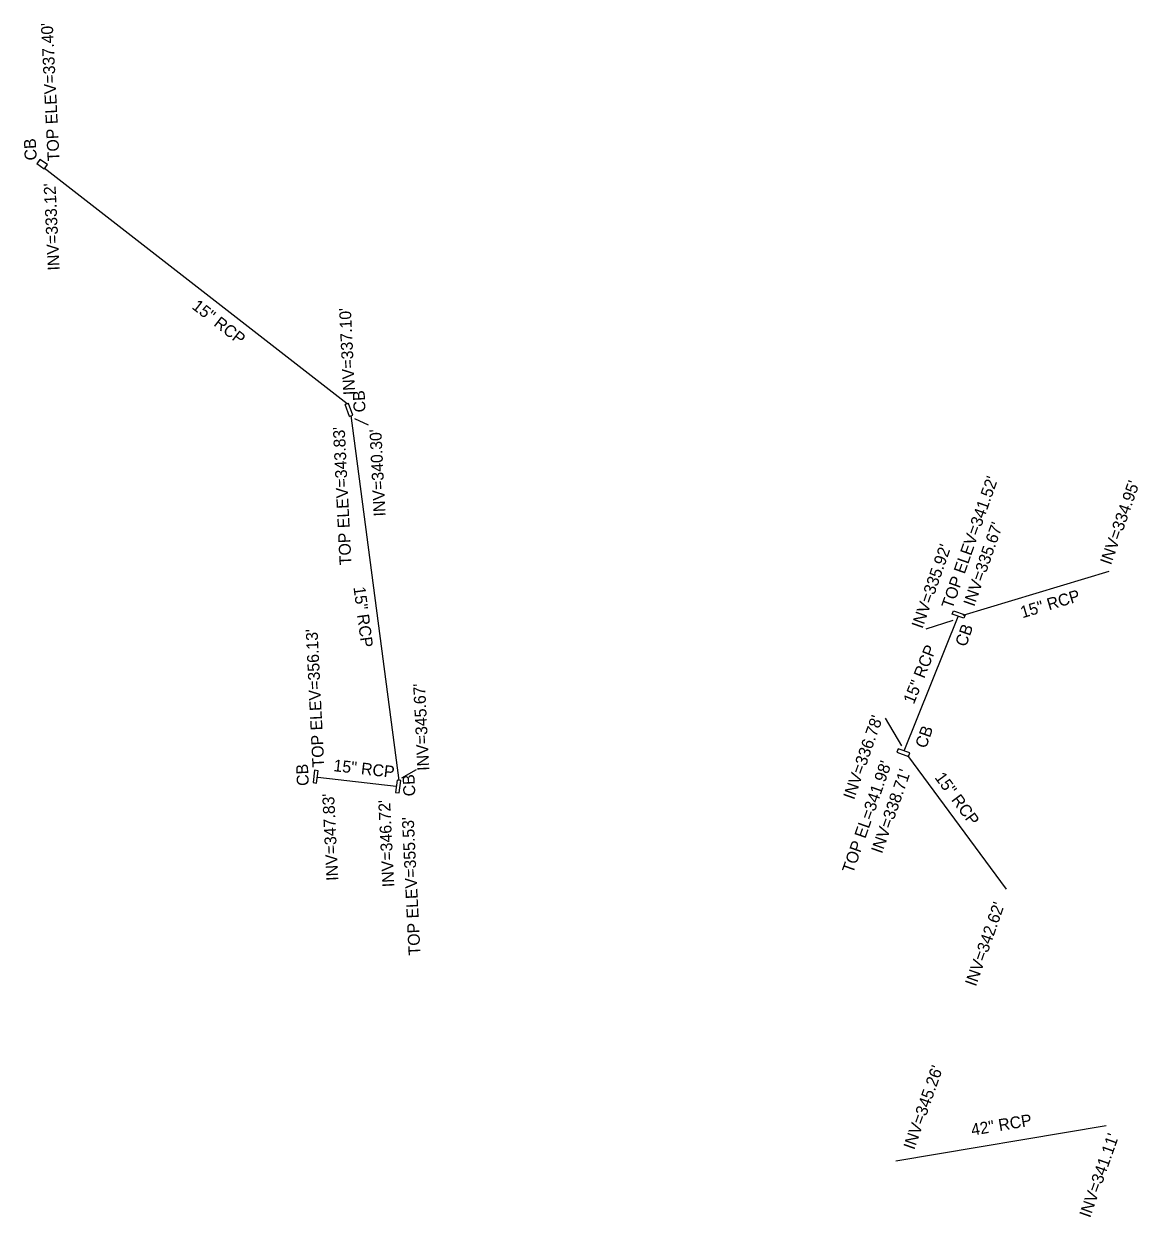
# Model space of a CAD drawing. Extents: x 1975859 to 1978323, y 778892 to 782836.
# Drawn here: x 1977337.6 to 1977712.6, y 781663.2 to 782064.9 of the extents above; entities that cross this region are included whole.
import ezdxf

# ---------------------------------------------------------------- set-up
doc = ezdxf.new("R2010")
doc.units = 0
for name, color, linetype in [('Exist Structure Minor Catch Basin', 7, 'Continuous'), ('Exist Structure Minor Catch Basin Text', 7, 'Continuous'), ('Exist Structure Minor Catch Basin Top Elevation', 7, 'Continuous'), ('Exist Structure Minor Pipes RCP 15 Inch', 7, 'Continuous'), ('Exist Structure Minor Pipes RCP 15 Inch Invert', 7, 'Continuous'), ('Exist Structure Minor Pipes RCP 15 Inch Leader', 7, 'Continuous'), ('Exist Structure Minor Pipes RCP 15 Inch Text', 7, 'Continuous'), ('Exist Structure Minor Pipes RCP 42 Inch', 7, 'Continuous'), ('Exist Structure Minor Pipes RCP 42 Inch Invert', 7, 'Continuous'), ('Exist Structure Minor Pipes RCP 42 Inch Text', 7, 'Continuous')]:
    doc.layers.add(name, color=color, linetype=linetype)

msp = doc.modelspace()

# ---------------------------------------------------------------- linework, layer by layer
at = {"layer": 'Exist Structure Minor Catch Basin'}
for p, q in [((1977344.43, 782015.95), (1977341.97, 782017.7)), ((1977447.15, 781932.75), (1977445.69, 781936.71)), ((1977650.44, 781867.32), (1977654.4, 781865.94)), ((1977631.41, 781819.67), (1977635.4, 781818.3)), ((1977436.11, 781809.29), (1977436.66, 781813.41)), ((1977463.93, 781805.98), (1977464.44, 781810.12))]:
    msp.add_line(p, q, dxfattribs=at)
for points in [[(1977344.43, 782015.95), (1977345.52, 782017.56), (1977342.95, 782019.22), (1977341.97, 782017.7)], [(1977447.15, 781932.75), (1977448.29, 781933.2), (1977446.81, 781937.1), (1977445.69, 781936.71)], [(1977654.4, 781865.94), (1977654.01, 781864.77), (1977650.02, 781866.14), (1977650.44, 781867.32)], [(1977635.4, 781818.3), (1977635.79, 781819.44), (1977631.84, 781820.82), (1977631.41, 781819.67)], [(1977436.66, 781813.41), (1977435.45, 781813.6), (1977434.93, 781809.44), (1977436.11, 781809.29)], [(1977464.44, 781810.12), (1977463.21, 781810.27), (1977462.7, 781806.12), (1977463.93, 781805.98)]]:
    msp.add_lwpolyline(points, dxfattribs=at)
at = {"layer": 'Exist Structure Minor Pipes RCP 15 Inch'}
for p, q in [((1977446.36, 781936.91), (1977344.46, 782016.26)), ((1977463.87, 781810.12), (1977447.72, 781933)), ((1977653.7, 781865.82), (1977702.94, 781880.59)), ((1977633.92, 781820.21), (1977652.04, 781865.35)), ((1977668.34, 781773.59), (1977635.08, 781818.56)), ((1977462.87, 781808.17), (1977436.48, 781811.14))]:
    msp.add_line(p, q, dxfattribs=at)
at = {"layer": 'Exist Structure Minor Pipes RCP 15 Inch Leader'}
for points in [[(1977448.83, 781931.99), (1977453.52, 781929.86)], [(1977650.22, 781864), (1977641.18, 781861.12)], [(1977633.06, 781821.82), (1977627.57, 781831.16)], [(1977464.76, 781811.07), (1977469.72, 781813.86)]]:
    msp.add_lwpolyline(points, dxfattribs=at)
at = {"layer": 'Exist Structure Minor Pipes RCP 42 Inch'}
msp.add_line((1977631.05, 781682.08), (1977701.89, 781694.05), dxfattribs=at)

# ---------------------------------------------------------------- texts
at = {"layer": 'Exist Structure Minor Catch Basin Text'}
for rotation, p in [(92.8374, (1977341.92, 782019)), (92.8374, (1977452.62, 781934.19)), (70.6265, (1977654.71, 781854.94)), (70.6265, (1977641.24, 781820.73)), (92.8374, (1977433.53, 781808.45)), (92.8374, (1977469.38, 781804.94))]:
    msp.add_text('CB', height=4, rotation=rotation, dxfattribs=at).set_placement(p)
at = {"layer": 'Exist Structure Minor Catch Basin Top Elevation'}
for s, rotation, p in [("TOP ELEV=337.40'", 92.8374, (1977349.6, 782018.73)), ("TOP ELEV=343.83'", 92.8374, (1977447.87, 781882.74)), ("TOP ELEV=341.52'", 70.6265, (1977650.08, 781867.68)), ("TOP ELEV=356.13'", 92.8374, (1977438.73, 781814.66)), ("TOP EL=341.98'", 70.6265, (1977616.64, 781778.63)), ("TOP ELEV=355.53'", 92.8374, (1977471.1, 781751.37))]:
    msp.add_text(s, height=4, rotation=rotation, dxfattribs=at).set_placement(p)
at = {"layer": 'Exist Structure Minor Pipes RCP 15 Inch Invert'}
for s, rotation, p in [("INV=333.12'", 92.8374, (1977349.66, 781981.95)), ("INV=337.10'", 92.8374, (1977449.1, 781939.99)), ("INV=340.30'", 92.8374, (1977459.34, 781899.15)), ("INV=334.95'", 70.6265, (1977703.47, 781882.49)), ("INV=335.67'", 70.6265, (1977657.45, 781868.48)), ("INV=335.92'", 70.6265, (1977640.01, 781861.06)), ("INV=345.67'", 92.8374, (1977474.05, 781813.54)), ("INV=336.78'", 70.6265, (1977617.01, 781803.47)), ("INV=338.71'", 70.6265, (1977626.4, 781785.32)), ("INV=347.83'", 92.8374, (1977443.44, 781776.5)), ("INV=346.72'", 92.8374, (1977462.29, 781774.36)), ("INV=342.62'", 70.6265, (1977658.02, 781740.6))]:
    msp.add_text(s, height=4, rotation=rotation, dxfattribs=at).set_placement(p)
at = {"layer": 'Exist Structure Minor Pipes RCP 15 Inch Text'}
for rotation, p in [(322.0914, (1977393.86, 781969.24)), (277.4912, (1977448.51, 781875.2)), (16.6939, (1977673.69, 781864.77)), (68.1314, (1977637.15, 781835.63)), (353.5688, (1977441.62, 781813.33)), (306.4875, (1977643.99, 781811.14))]:
    msp.add_text('15" RCP', height=4, rotation=rotation, dxfattribs=at).set_placement(p)
at = {"layer": 'Exist Structure Minor Pipes RCP 42 Inch Invert'}
for s, p in [("INV=345.26'", (1977637.27, 781685.61)), ("INV=341.11'", (1977696.48, 781662.72))]:
    msp.add_text(s, height=4, rotation=70.6265, dxfattribs=at).set_placement(p)
at = {"layer": 'Exist Structure Minor Pipes RCP 42 Inch Text'}
msp.add_text('42" RCP', height=4, rotation=9.5902, dxfattribs=at).set_placement((1977656.76, 781690.58))

doc.saveas('drawing.dxf')
